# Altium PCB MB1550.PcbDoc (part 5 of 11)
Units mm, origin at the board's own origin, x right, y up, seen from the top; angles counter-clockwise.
Board outline 154.81 x 170.69 mm, 6 copper layers (Top Layer, Signal Layer 1, Signal Layer 2, Signal Layer 3, Signal Layer 4, Bottom Layer), stack 1.49 mm thick; 810 components, 633 nets, 2973 pads, 2150 vias.
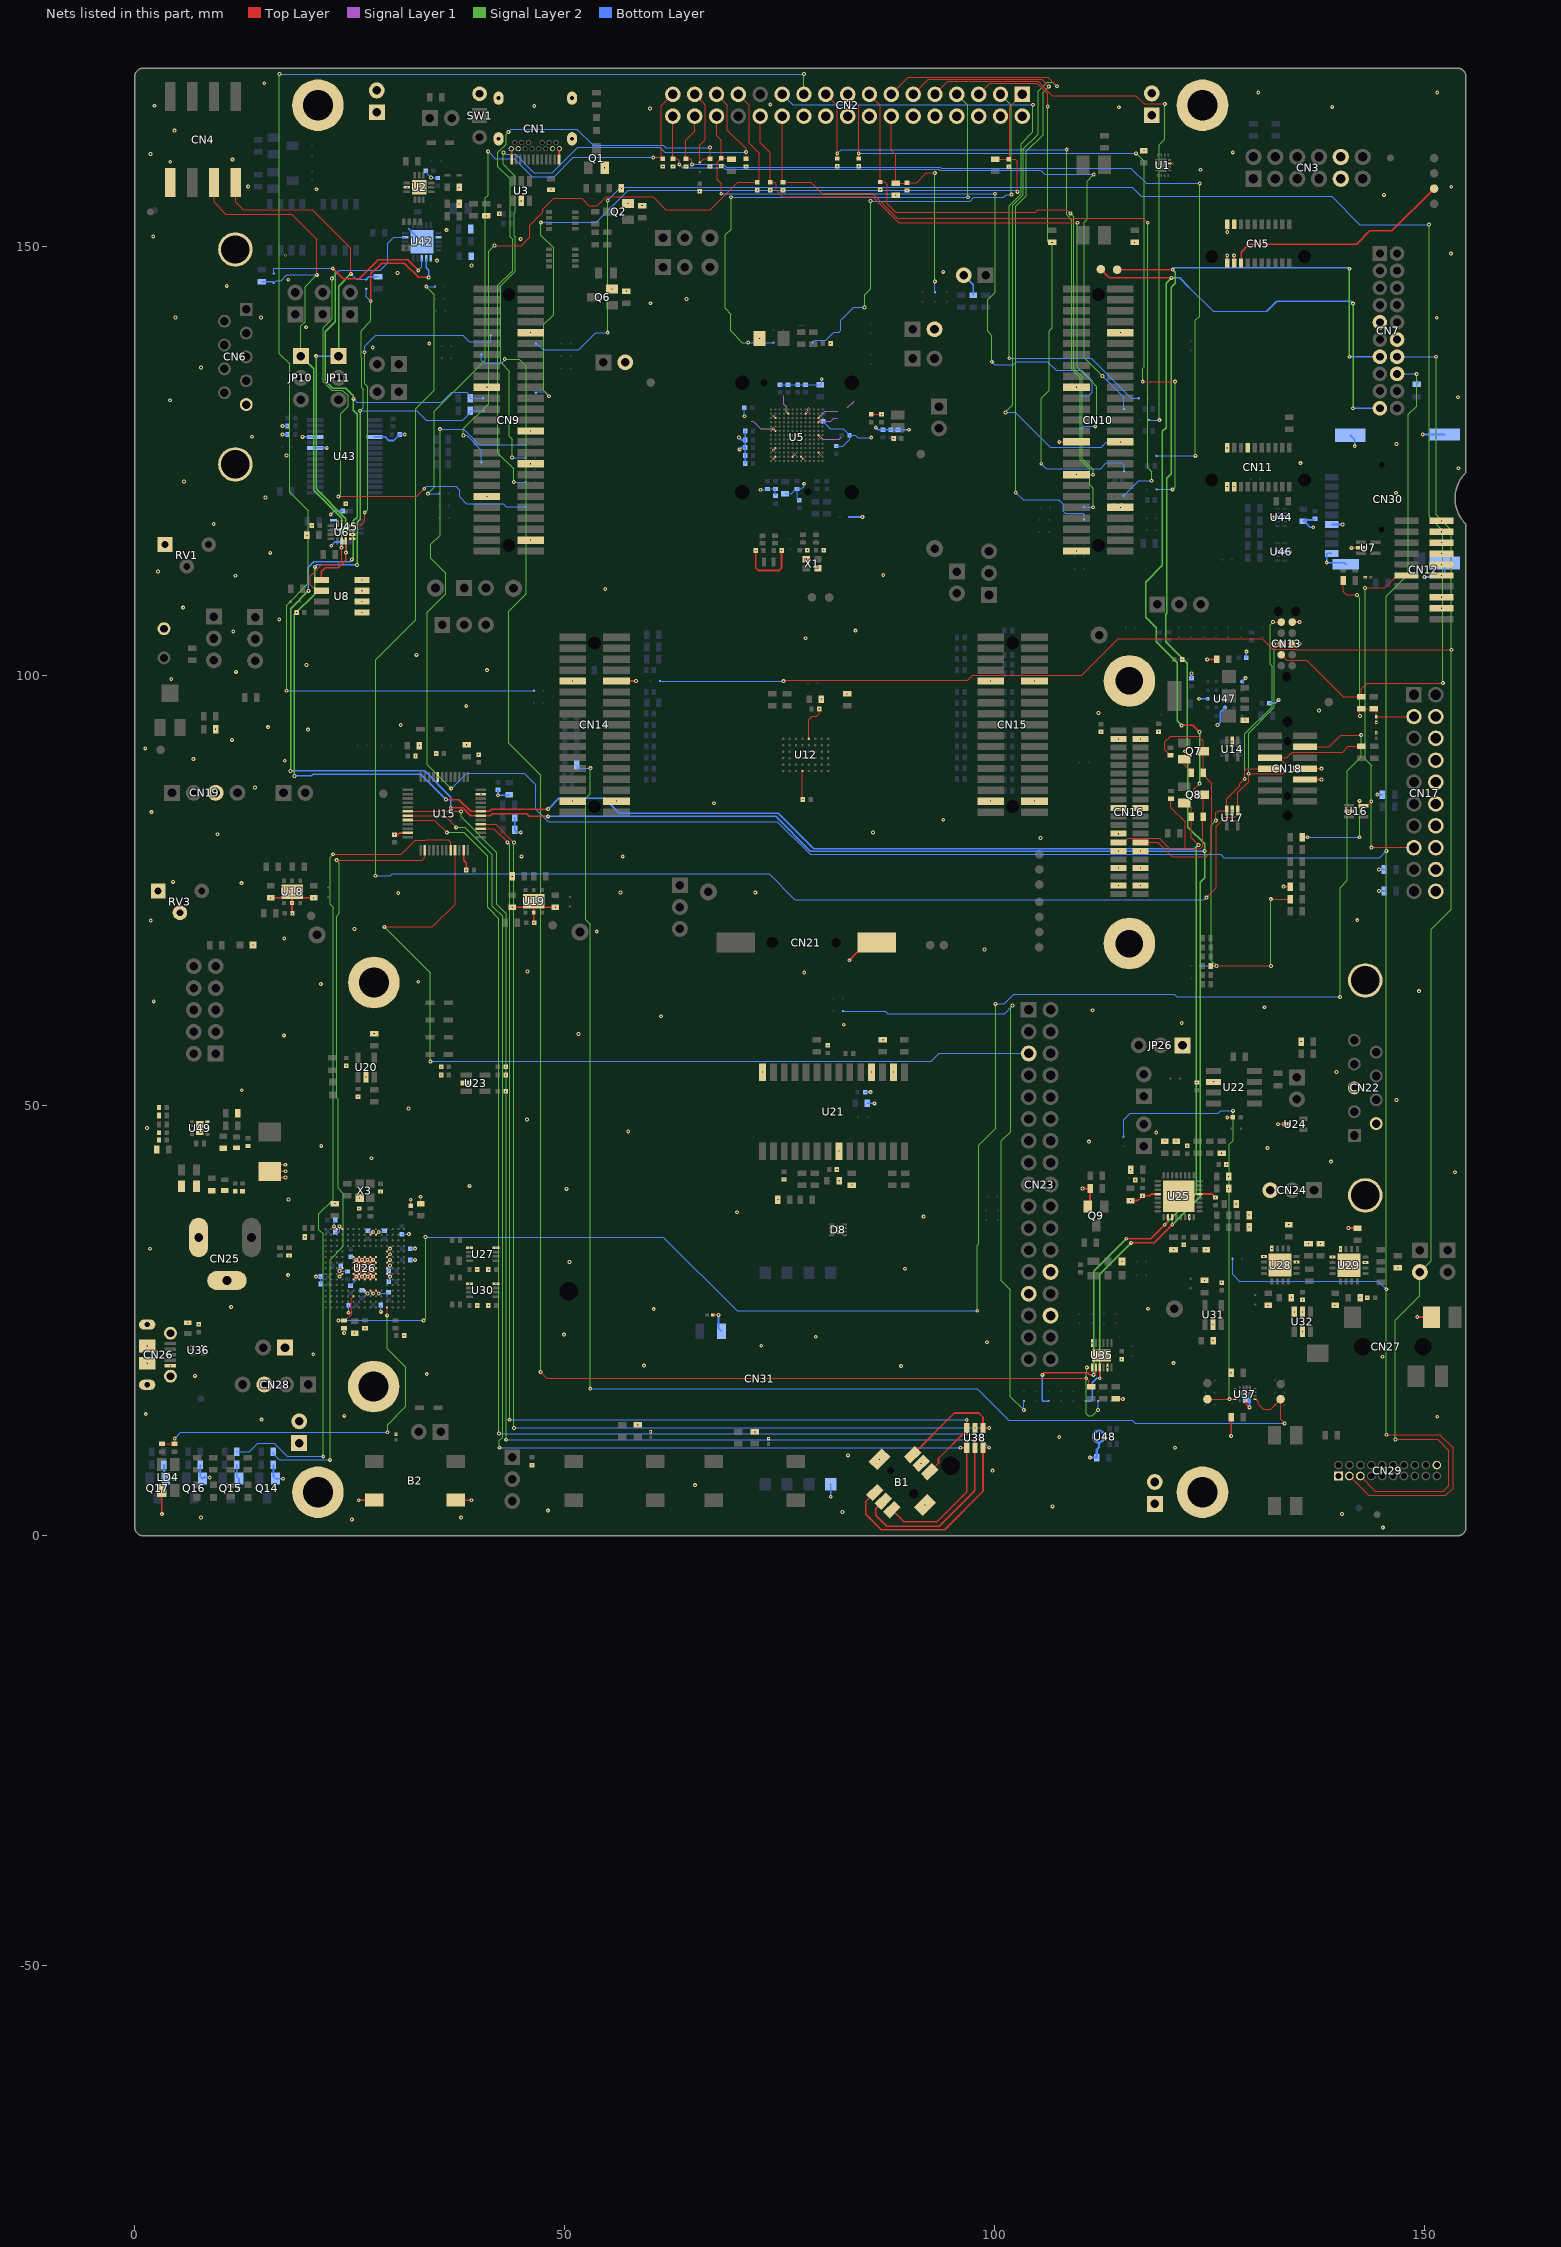
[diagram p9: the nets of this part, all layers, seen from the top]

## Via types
v1: diameter 0.45, hole 0.2, Top Layer to Bottom Layer, tented both sides, 1777 vias
v2: diameter 0.25, hole 0.1, Top Layer to Signal Layer 1, tented top, 344 vias
v3: diameter 0.25, hole 0.1, Signal Layer 1 to Signal Layer 2, 29 vias

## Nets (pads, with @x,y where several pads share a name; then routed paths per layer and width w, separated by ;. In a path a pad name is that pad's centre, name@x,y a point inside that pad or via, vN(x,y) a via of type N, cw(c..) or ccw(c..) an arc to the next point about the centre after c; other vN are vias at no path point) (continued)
GND: B1.5 B1.7 B1.8 B2.3 B2.4 C1.1 C2.1 C3.1 C4.2 C5.1 C6.2 C7.1 C8.2 C9.2 C10.2 C11.2 C12.1 C13.1 C14.1 C15.1 C16.1 C17.2 C18.1 C20.2 C21.2 C22.1 C23.1 C24.1 C25.1 C26.1 C27.1 C28.2 C29.2 C30.2 C31.2 C32.1 C33.1 C34.1 C35.1 C36.1 C37.1 C38.1 C39.1 C40.2 C41.1 C42.1 C43.1 C44.1 C45.1 C46.1 C47.1 C48.1 C49.1 C50.2 C51.2 C52.2 C54.2 C55.2 C56.1 C57.1 C58.2 C59.2 C60.2 C61.2 C62.1 C63.2 C64.2 C65.2 C67.2 C68.2 C69.1 C70.2 C71.2 C72.1 C73.1 C74.1 C75.2 C76.1 C77.1 C78.2 C79.2 C80.1 C81.1 C82.2 C83.2 C85.1 C87.2 C89.1 C90.2 C91.1 C94.2 C95.1 C96.1 C97.1 C98.2 C99.1 C100.1 C101.2 C102.2 C103.1 C104.2 C105.1 C106.1 C107.1 C108.1 C109.1 C110.2 C111.1 C112.1 C113.1 C116.2 C117.1 C118.1 C119.1 C120.1 C121.1 C122.1 C123.1 C124.1 C127.1 C128.1 C129.1 C130.1 C131.1 C132.1 C133.2 C134.1 C135.1 C136.1 C137.1 C138.1 C139.1 C142.1 C143.1 C144.1 C145.2 C146.1 C147.1 C150.2 C151.1 C152.1 C153.2 C154.1 C155.1 C156.1 C157.1 C158.2 C159.2 C160.1 C161.2 C162.2 C163.2 C164.2 C165.2 C166.2 C167.2 C168.2 C169.2 C170.2 C171.1 C172.2 C173.2 C174.2 C175.2 C176.2 C177.1 C178.2 C179.2 C180.1 C181.2 C185.1 C186.1 C187.1 C188.1 C189.1 CN1.A1 CN1.A12 CN1.B1 CN1.B12 CN1.SH1 CN1.SH2 CN1.SH3 CN1.SH4 CN2.2 CN2.4 CN2.6 CN2.8 CN2.10 CN2.12 CN2.16 CN2.18 CN2.20 CN2.22 CN3.5 CN3.11 CN4.2 CN5.17 CN5.18 CN5.19 CN5.20 CN6.5 CN6.MT1 CN6.MT2 CN7.5 CN7.16 CN8.2 CN9.10 CN9.19 CN9.28 CN9.34 CN9.39 CN9.48 CN10.10 CN10.19 CN10.29 CN10.30 CN10.35 CN10.42 CN10.49 CN11.13 CN11.18 CN11.19 CN11.20 CN12.3 CN12.5 CN12.9 CN12.11 CN12.13 CN12.15 CN12.17 CN12.19 CN13.3 CN13.5 CN14.9 CN14.10 CN14.31 CN14.32 CN15.9 CN15.10 CN15.31 CN15.32 CN16.3 CN16.4 CN16.7 CN16.8 CN16.11 CN16.12 CN16.16 CN16.21 CN16.22 CN16.37 CN16.38 CN16.41 CN16.42 CN17.4 CN17.6 CN17.8 CN17.10 CN17.12 CN17.14 CN17.16 CN17.18 CN17.20 CN18.5 CN18.7 CN19.3 CN21.2 CN22.3 CN22.6 CN22.MT1 CN22.MT2 CN23.26 CN23.27 CN23.30 CN24.3 CN26.5 CN26.6 CN26.7 CN26.8 CN26.9 CN26.10 CN26.11 CN27.3 CN28.3 CN29.1 CN29.20 CN30.6 CN30.9 CN30.11 CN30.12 CN30.13 CN30.14 CN31.C5 CN31.S1 D8.9 H1.1 H2.1 H3.1 H4.1 H5.1 H6.1 JP1.1 JP1.2 JP2.1 JP2.2 JP9.2 JP13.2 JP26.1 JP32.1 JP33.1 JP33.2 JP36.1 JP36.2 L3.1 LD2.2 LD4.1 Q1.2 Q2.2 Q6.2 Q9.2 Q14.2 Q15.2 Q16.2 Q17.2 R7.1 R9.2 R10.2 R12.1 R13.1 R16.1 R17.1 R20.1 R33.1 R38.2 R42.1 R44.1 R45.1 R60.1 R61.1 R73.1 R75.1 R77.1 R84.1 R85.1 R88.1 R93.1 R94.1 R96.1 R98.1 R99.1 R101.2 R102.2 R105.1 R107.1 R109.1 R115.1 R117.1 R118.2 R121.1 R122.2 R124.1 R126.1 R141.1 R230.1 R233.1 R234.1 R235.1 R236.1 R241.1 R242.1 R243.1 R244.1 R250.1 R251.1 R252.2 RV1.1 RV3.1 RV3.2 SB2.2 SB76.1 SW1.3 U1.11 U2.2 U2.13 U3.2 U4.2 U5.B2 U5.B4 U5.B8 U5.B11 U5.E12 U5.F2 U5.H2 U5.J12 U5.M3 U5.M7 U5.M10 U5.M11 U6.1 U6.2 U6.3 U6.6 U6.7 U7.2 U8.1 U8.2 U8.3 U8.4 U9.2 U11.2 U12.D1 U12.E6 U13.2 U14.2 U15.8 U15.23 U15.35 U15.47 U16.2 U17.2 U18.2 U18.EP U19.2 U19.EP U20.2 U21.2 U21.4 U21.14 U21.22 U22.2 U23.2 U24.3 U25.7 U25.13 U25.28 U25.33 U26.D5 U26.D6 U26.D7 U26.D8 U26.D9 U26.F2 U26.F6 U26.F7 U26.F8 U26.F9 U26.F10 U26.F12 U26.G2 U26.G6 U26.G7 U26.G8 U26.G9 U26.G10 U26.G12 U26.H6 U26.H7 U26.H8 U26.H9 U26.H10 U26.H12 U26.J6 U26.J7 U26.J8 U26.J9 U26.J10 U26.K6 U26.K7 U26.K8 U26.K9 U26.K10 U26.M1 U26.M8 U26.M9 U26.N1 U27.4 U27.5 U28.7 U28.12 U28.13 U28.17 U29.7 U29.12 U29.13 U29.17 U30.4 U30.5 U31.2 U32.2 U32.5 U32.6 U33.2 U34.2 U35.6 U35.11 U35.13 U36.3 U37.11 U38.2 U39.2 U40.2 U41.2 U42.12 U42.16 U42.21 U43.4 U43.23 U43.25 U44.3 U44.8 U45.4 U46.3 U46.8 U47.B3 U47.C1 U47.E5 U48.3 U49.8 U49.9 U51.2 X1.2 X1.4 X3.2 | length 267.7
  Top Layer w0.08: U5.F2@76.5,125.5 v2(76.75,125.75)
  Top Layer w0.1: v1(24.35,23.586) R117.1@24.35,24.15 ; C82.2@32.1,38.4 v1(32.1,39.095) ; C81.1@33.25,38.65 v1(33.25,39.434) ; U12.D1@77.65,88.946 77.65,85.675 v2(77.7,85.625) ; U12.E6@78.4,92.696 78.4,94.925 78.775,95.3 79.3,95.3 79.6,95.6 v2(79.6,96.15) ; C23.1@85.655,130.427 C22.1@86.825,130.427
  Top Layer w0.2: v1(3.15,2.524) LD4.1@3.15,5.3 ; v2(15.8,74.2) 17.85,74.2 U18.EP@18.3,74.65 ; v1(17.513,43.154) 16.5,43.154 C60.2@15.743,42.397 ; v1(17.534,42.397) C60.2@15.743,42.397 ; v1(17.539,41.666) 16.385,41.666 C60.2@15.699,42.353 C60.2@15.743,42.397 ; v2(18.35,72.4) 18.3,72.45 v2(18.3,73.6) U18.EP@18.3,74.65 ; v2(20.8,74.2) 18.75,74.2 U18.EP@18.3,74.65 ; v1(23.175,36) U26.N1@23.5,35.675 ; v1(23.825,30.15) U26.M9@24.15,30.475 ; v1(23.825,30.8) U26.M8@24.15,31.125 ; v1(23.825,36) U26.M1@24.15,35.675 ; U26.K10@25.45,29.825 v1(25.775,30.15) ; v1(25.775,30.15) U26.J10@26.1,29.825 v1@26.425,30.15 ; v1(26.05,4.15) B2.3@27.85,4.15 ; v1(26.425,30.15) U26.H10@26.75,29.825 v1(27.075,30.15) U26.H9@26.75,30.475 ; U26.H12@26.75,28.525 v1(27.075,28.2) ; U26.G12@27.4,28.525 v1(27.725,28.2) ; U26.G2@27.4,35.025 v1(27.725,35.35) ; U26.F7@28.05,31.775 v1(27.725,32.1) ; U26.F2@28.05,35.025 v1(28.375,35.35) ; U26.F12@28.05,28.525 v1(28.375,28.2) ; U26.F10@28.05,29.825 v1(27.725,30.15) ; U26.F7@28.05,31.775 v1(27.725,31.45) ; U26.F6@28.05,32.425 v1(27.725,32.1) ; U26.D9@29.35,30.475 v1(29.675,30.15) ; U26.D8@29.35,31.125 v1(29.675,31.45) ; U26.D7@29.35,31.775 v1(29.675,32.1) ; U26.D6@29.35,32.425 v1(29.675,32.75) ; U26.D5@29.35,33.075 v1(29.675,33.4) ; v2(30.2,81.55) 30.6,81.55 30.8,81.75 U15.23@31.748,81.75 ; B2.4@37.35,4.15 v1(39.15,4.15) ; U15.35@38.248,79.75 38.248,78.577 38.55,78.275 v2(38.55,77.45) ; CN1.B1@43.79,161.32 43.84,161.27 CN1.A12@43.84,160.07 ; v2(43.9,73.1) 45.7,73.1 v2(46.4,73.8) ; v2(46.45,71.3) 46.4,71.35 U19.2@46.4,72.5 v2(46.4,73.8) ; v2(48.9,73.1) 47.1,73.1 v2(46.4,73.8) ; CN1.A1@49.34,160.07 49.34,161.27 CN1.B12@49.39,161.32 ; CN14.10@56.025,99.41 v1(58.295,99.41) ; U33.2@67.213,25.7 v1(67.88,25.7) ; v2(72.225,114.6) 72.225,112.564 72.514,112.275 74.95,112.275 75.225,112.55 v2(75.225,114.6) ; v2(74.25,125.25) U5.B2@74.5,125.5 ; v2(74.25,126.25) U5.B4@74.5,126.5 ; v2(74.25,128.75) U5.B8@74.5,128.5 ; v2(74.25,130.25) U5.B11@74.5,130 ; v2(75.75,130.75) U5.E12@76,130.5 ; U5.H2@77.5,125.5 v2(77.75,125.25) ; U5.J12@78,130.5 v2(78.25,130.75) ; U5.M3@79.5,126 v2(79.75,125.75) ; U5.M7@79.5,128 v2(79.75,127.75) ; U5.M10@79.5,129.5 v2(79.75,129.75) ; U5.M11@79.5,130 v2(79.75,130.25) ; v1(83.104,66.934) 85.17,69 CN21.2@86.283,69 ; C22.1@86.825,130.427 v2(86.83,130.427) ; v1(107.52,127.225) CN10.29@109.523,127.225 ; v1(110.217,40.4) R93.1@111.1,40.4 111.1,38.55 Q9.2@110.85,38.3 ; R121.1@114.1,15.925 v1(114.908,15.925) ; v2(115.8,39) 116.65,39 C78.2@117.2,39.55 118.025,39.55 118.225,39.75 U25.28@118.975,39.75 ; U1.11@120.35,159.6 v2(120.7,159.6) ; U25.13@123.825,39.75 125.3,39.75 v2(125.7,39.35) ; v1(124.711,101.925) C33.1@125.85,101.925 ; v1(127.046,48.675) C63.2@127.7,48.675 ; CN5.20@127.05,148.025 v1(127.05,148.896) ; v1(127.05,151.625) CN5.19@127.05,152.525 ; v1(127.5,11.625) R122.2@127.5,13.8 ; CN5.18@127.85,148.025 v1(127.85,148.896) ; U37.11@129.3,15.725 129.3,15.275 v1(129.625,14.95) ; v1(132.955,47.875) U24.3@133.975,47.875 ; v1(133.582,75.5) R61.1@134.35,75.5 ; CN13.3@134.61,103.725 v1(135.468,103.725) ; CN13.5@134.61,106.265 v1(135.468,106.265) ; CN18.5@136.082,87.955 v1(138.015,87.955) ; CN18.7@136.082,89.225 v1(138.015,89.225) ; v1(141.143,35.8) C87.2@142.2,35.8 ; v1(141.514,114.9) U7.2@142.6,114.9 ; v1(149.152,25.45) CN27.3@150.8,25.45 ; U26.K8@25.45,31.125 v1(25.775,31.45) ; U26.K8@25.45,31.125 v1(25.775,30.8) ; U26.K8@25.45,31.125 v1(25.775,30.8) ; U26.K7@25.45,31.775 v1(25.775,32.1) ; U26.K7@25.45,31.775 v1(25.775,31.45) ; U26.K7@25.45,31.775 v1(25.775,31.45) ; v1(25.775,30.15) U26.K9@25.45,30.475 v1(25.775,30.8) ; v1(25.775,30.15) U26.J9@26.1,30.475 ; v1(25.775,30.8) U26.J9@26.1,30.475 ; v1(25.775,30.8) U26.J8@26.1,31.125 ; v1(25.775,31.45) U26.J7@26.1,31.775 ; v1(25.775,31.45) U26.J8@26.1,31.125 ; v1(25.775,32.1) U26.K6@25.45,32.425 v1(25.775,32.1) ; v1(25.775,32.1) U26.J7@26.1,31.775 ; v1(25.775,32.1) U26.J6@26.1,32.425 ; U26.J9@26.1,30.475 v1@26.425,30.8 ; U26.J9@26.1,30.475 v1@26.425,30.15 ; U26.J9@26.1,30.475 v1@26.425,30.15 ; U26.J8@26.1,31.125 v1@26.425,30.8 ; U26.J8@26.1,31.125 v1@26.425,30.8 ; U26.J8@26.1,31.125 v1@26.425,31.45 ; U26.J7@26.1,31.775 v1@26.425,32.1 ; U26.J7@26.1,31.775 v1@26.425,31.45 ; U26.J7@26.1,31.775 v1@26.425,31.45 ; U26.J6@26.1,32.425 v1@26.425,32.1 ; U26.J6@26.1,32.425 v1@26.425,32.1 ; v1@26.425,30.15 U26.H9@26.75,30.475 ; v1(26.425,30.8) U26.H9@26.75,30.475 ; v1@26.425,30.8 U26.H8@26.75,31.125 ; v1@26.425,31.45 U26.H8@26.75,31.125 ; v1@26.425,31.45 U26.H7@26.75,31.775 ; v1(26.425,32.1) U26.H7@26.75,31.775 ; v1@26.425,32.1 U26.H6@26.75,32.425 ; U26.H9@26.75,30.475 v1(27.075,30.8) ; U26.H9@26.75,30.475 v1(27.075,30.15) ; U26.H8@26.75,31.125 v1(27.075,30.8) ; U26.H8@26.75,31.125 v1(27.075,31.45) ; U26.H8@26.75,31.125 v1(27.075,30.8) ; U26.H7@26.75,31.775 v1(27.075,32.1) ; U26.H7@26.75,31.775 v1(27.075,31.45) ; U26.H7@26.75,31.775 v1(27.075,31.45) ; U26.H6@26.75,32.425 v1(27.075,32.1) ; U26.H6@26.75,32.425 v1(27.075,32.1) ; v1(27.075,30.15) U26.G9@27.4,30.475 ; v1(27.075,30.15) U26.G10@27.4,29.825 v1(27.725,30.15) ; v1(27.075,30.8) U26.G9@27.4,30.475 ; v1(27.075,30.8) U26.G8@27.4,31.125 ; v1(27.075,30.8) U26.G9@27.4,30.475 ; v1(27.075,31.45) U26.G8@27.4,31.125 ; v1(27.075,31.45) U26.G7@27.4,31.775 ; v1(27.075,32.1) U26.G7@27.4,31.775 ; v1(27.075,32.1) U26.G6@27.4,32.425 v1(27.725,32.1) ; U26.G9@27.4,30.475 v1(27.725,30.8) ; U26.G9@27.4,30.475 v1(27.725,30.15) ; U26.G9@27.4,30.475 v1(27.725,30.15) U26.F9@28.05,30.475 v1(27.725,30.8) ; U26.G8@27.4,31.125 v1(27.725,31.45) ; U26.G8@27.4,31.125 v1(27.725,30.8) ; U26.G8@27.4,31.125 v1(27.725,30.8) ; U26.G7@27.4,31.775 v1(27.725,32.1) ; U26.G7@27.4,31.775 v1(27.725,31.45) ; U26.G7@27.4,31.775 v1(27.725,31.45) ; v1(27.725,30.8) U26.F8@28.05,31.125 v1(27.725,31.45)
  Signal Layer 1 w0.08: 71.675,129.65 71.92,129.65 72.82,128.75 v2(74.25,128.75) ; v2(75.75,130.75) 75.75,131.364 ; v2(78.25,130.75) 78.25,131.075 78.4,131.225 ; v2(79.75,127.75) 79.993,127.507 81.915,127.507 82.171,127.763 ; 82.885,131.163 83.698,131.976
  Signal Layer 1 w0.1: 75.5,132.6 75.5,131.614 75.75,131.364 ; v2(79.75,129.75) 79.86,129.64 80.915,129.64 81.275,130 81.725,130 ; v2(79.75,130.25) 80.31,130.81 81.76,130.81
  Bottom Layer w0.08: v1(70.9,130.206) C123.1@70.9,131.2 ; C122.1@75.025,133.875 C121.1@75.975,133.875 C120.1@77.1,133.875 C119.1@78,133.875 C118.1@79.725,133.875 79.899,134.049 v1(79.899,134.505) ; C136.1@81.577,126.743 82.328,126.743 83.125,127.54 C134.1@83.125,128 83.794,128 84.076,127.718 v1(85.65,127.718)
  Bottom Layer w0.1: v1(21.075,30.15) C172.2@21.65,30.15 C174.2@21.65,29.3 ; v1(23.175,36) 23.175,36.6 C161.2@23.3,36.725 ; C165.2@23.3,35.325 23.7,35.325 23.825,35.45 v1(23.825,36) ; C169.2@23.95,31.375 23.825,31.25 v1(23.825,30.8) 24.525,30.8 C171.1@24.6,30.725 ; v1(24.875,25.95) C179.2@24.875,26.825 ; C175.2@25.075,29.1 25.775,29.8 v1(25.775,30.15) ; C167.2@25.125,32.45 25.475,32.1 v1(25.775,32.1) ; C176.2@26.425,28.55 26.425,28.525 26.75,28.2 v1(27.075,28.2) ; C164.2@27.1,35.475 27.225,35.35 v1(27.725,35.35) ; v1(28.375,28.2) 29.372,28.2 C177.1@29.493,28.32 ; v1(28.375,35.35) 28.925,35.35 C163.2@29.05,35.475 ; v1(28.625,26.05) C178.2@28.625,26.85 ; C173.2@29.55,29.55 29.675,29.675 v1(29.675,30.15) ; C170.2@29.55,30.8 29.675,30.925 v1(29.675,31.45) ; C162.2@31.05,35.1 v1(31.875,35.1) ; C168.2@32.025,32.1 v1(32.6,32.1) ; C166.2@32.025,33.4 v1(32.6,33.4) ; C144.1@73.575,121.75 74.437,121.75 C143.1@74.467,121.721 ; C143.1@74.5,121.75 74.5,121.089 C146.1@74.563,121.026 ; C145.2@75.625,121.175 76.367,121.175 C142.1@76.78,121.588 ; C142.1@77.068,121.78 C142.1@77.068,121.75 ; C142.1@77.185,121.935 C142.1@77,121.75 C142.1@77.068,121.75 ; C147.1@77.275,120.45 77.068,120.657 C142.1@77.068,121.75 ; v1(77.85,122.35) 77.85,122.075 77.525,121.75 C142.1@77.068,121.75 ; C124.1@80.022,129.624 80.885,128.76 82.365,128.76 C134.1@83.125,128
  Bottom Layer w0.12: C112.1@33.83,158.763 34.019,158.574 34.019,158.402 v1(34.457,157.963) 35.176,157.963 C113.1@35.234,157.906
  Bottom Layer w0.13: v1(72.775,121.65) 73.469,121.65 73.472,121.647 C144.1@73.575,121.75
  Bottom Layer w0.2: R244.1@3.4,8.275 3.4,6.875 Q17.2@3.625,6.65 v1(4.5,6.65) ; R243.1@7.625,8.275 7.625,6.9 Q16.2@7.875,6.65 8.025,6.8 v1(8.725,6.8) ; R242.1@11.875,8.275 11.875,6.9 Q15.2@12.125,6.65 v1(12.125,5.55) ; R241.1@16.125,8.275 16.125,6.9 Q14.2@16.375,6.65 v1(17.25,6.65) ; v1(17.2,128.075) C133.2@17.8,128.075 ; v1(17.2,129.075) C127.1@17.8,129.075 ; v1(19.511,127.811) U43.25@20.976,127.811 ; U43.23@20.976,126.511 20.99,126.525 v1(22.325,126.525) ; v1(22.795,118.791) 23.178,119.175 C151.1@24.2,119.175 ; v1(22.85,115.15) 23.275,115.575 C153.2@24.15,115.575 ; U43.4@27.876,127.811 29.114,127.811 29.55,127.375 30.1,127.375 C132.1@30.8,128.075 v1(31.4,128.075) ; 31.875,152.025 U42.21@33.4,150.5 U42.21@33.475,150.5 ; C158.2@42.25,86.75 v1(42.25,86.125) 43.475,86.125 C157.1@43.55,86.2 ; R234.1@44.2,82.125 44.327,81.998 44.327,81.819 v1(44.896,81.819) ; R234.1@44.2,82.125 R233.1@44.2,83.575 ; v1(67.88,25.7) 67.88,24.16 CN31.S1@68.24,23.8 ; v1(70.283,127.732) 70.565,127.45 C135.1@71,127.45 ; v1(70.349,126.352) 70.572,126.575 C137.1@71,126.575 ; C139.1@71,124.725 C138.1@71,125.65 C137.1@71,126.575 ; C131.1@71,128.5 C135.1@71,127.45 ; v1(80.94,4.544) v2(80.94,6) ; SB76.1@83.1,118.475 v1(84.619,118.475) ; C159.2@84.95,51.6 v1(85.584,51.6) ; C160.1@85.2,50.3 v1(86.013,50.3) ; v1(86.171,128.914) 86.448,128.637 C129.1@87.013,128.637 C128.1@87.913,128.637 C130.1@88.763,128.637 v1(90.021,128.637) ; CN8.2@96.405,146.6 97.525,145.48 C117.1@97.525,144.3 ; C155.1@122.9,99.725 v1(122.9,100.3) ; v1(123.784,97.346) U47.C1@124.784,97.346 ; v1(125.925,94.3) 126.275,94.65 126.275,95.837 U47.B3@126.784,96.346 ; U47.E5@128.784,99.346 v1(129.188,99.75) ; C154.1@129.275,102.125 v1(129.275,102.825) ; C180.1@129.3,15.8 129.625,15.8 v1(129.625,14.95) ; C156.1@131.95,96.825 132.625,96.825 v1(133.025,97.225) ; v1(132.35,118.45) U44.3@132.915,118.45 U44.8@133.735,118.45 ; U46.3@132.915,114.425 U46.8@133.735,114.425 v1(134.375,114.425) ; v1(137.05,117.3) 136.675,117.3 136.225,117.75 136.225,117.8 136.025,118 C150.2@135.9,118 136.05,118.15 137.125,118.15 C152.1@137.25,118.275 ; CN30.9@139.198,114.262 138.685,114.262 138.625,114.202 v1(138.625,113.175) 140.66,113.175 CN30.14@140.848,112.987 ; CN30.6@139.198,117.612 v1(140.462,117.612) ; CN30.13@141.348,127.987 141.875,127.46 v1(141.875,126.725) ; v1(144.5,86.2) R230.1@145.1,86.2 ; v1(144.7,75) R236.1@145.3,75 ; v1(144.7,77.5) R235.1@145.3,77.5 ; v1(149.788,128.087) CN30.12@152.348,128.087 ; v1(149.975,111.5) 151.925,111.5 152.348,111.923 CN30.11@152.348,113.137 ; C137.1@71,126.575 C135.1@71,127.45
  Bottom Layer w0.25: v1(111.075,9.1) C181.2@111.875,9.1 111.875,10.025 112.125,10.275 112.125,10.805
  other v1: 145.142,0.958 25.253,1.898 7.702,2.145 37.959,2.145 140.395,2.54 82.305,2.788 48.044,2.936 106.728,3.43 65.15,5.902 99.757,7.583 82.948,9.363 120.966,10.253 107.519,11.489 14.723,13.516 151.47,13.862 24.363,13.961 1.275,14.158 7.01,18.608 33.954,18.806 89.128,19.745 59.217,19.794 120.818,20.091 145.092,20.833 20.754,21.129 72.862,22.118 99.114,22.514 79.191,23.156 49.923,23.403 60.354,26.37 117.851,26.419 11.213,26.617 17.837,30.325 89.573,31.066 26.425,31.45 50.566,31.857 1.77,33.39 91.748,37.147 70.044,37.642 17.887,39.125 50.22,40.361 38.948,40.707 153.546,42.289 139.11,43.525 27.527,43.92 131.744,45.107 21.694,45.354 110.979,45.849 118.8,46.9 57.388,47.035 1.424,47.431 45.622,48.419 31.828,49.705 146.724,50.694 12.449,51.831 139.753,53.956 17.343,58.208 51.604,58.356 82.453,59.444 121.757,59.642 61.195,60.433 111.375,61.125 131.398,61.471 2.215,62.163 149.344,63.35 21.644,64.19 32.966,64.437 77.856,65.525 45.671,65.624 98.818,68.195 17.392,69.48 53.73,70.271 25.55,70.568 1.869,71.557 142.175,71.606 30.642,74.77 56.498,74.819 72.17,74.819 12.399,75.907 4.439,76.055 44.979,79.022 56.745,79.022 105.344,81.148 9.631,81.593 85.865,81.79 94.022,83.273 1.968,84.163 67.375,85.202 13.981,87.031 17.442,90.145 6.813,90.343 1.226,91.579 11.311,92.568 20.161,93.754 15.514,94.051 30.939,94.298 112.067,95.683 137.726,95.979 38.552,96.523 4.242,99.638 11.756,100.478 40.975,100.676 19.963,101.269 32.768,102.456 78.004,104.384 11.46,105.175 83.838,105.274 16.799,106.559 5.626,107.943 54.718,110.119 11.707,111.651 87.051,111.75 2.709,112.146 15.761,114.321 9.186,117.683 15.217,120.748 146.674,121.292 5.725,122.627 153.942,124.159 135.55,124.752 17.64,125.642 146.724,126.977 13.635,127.818 4.093,132.069 153.892,132.415 7.702,135.876 27.676,138.2 34.251,138.645 19.93,140.547 151.42,141.66 4.75,141.694 14.675,141.675 59.959,143.341 64.161,143.836 10.708,145.364 17.85,146.075 30.55,146.875 94.025,147 39.166,147.725 35.15,148.3 153.052,149.126 44.88,150.807 2.16,151.106 36.275,151.85 145.29,155.948 21.119,156.604 153.101,156.887 13.188,156.929 123.932,158.865 4.125,159.8 11.355,160.042 1.844,160.709 127.69,160.892 4.623,163.415 59.91,165.984 114.44,166.132 139.258,166.182 46.462,166.281 2.312,166.317 73.901,166.479 130.656,167.863 151.47,167.863 15.068,168.935
  other v2: 91.908,3.592 46.2,8.225 91.449,8.435 86.605,8.895 73.7,11.312 30.4,11.839 72.1,12.1 60,12.112 97.7,12.55 58.5,12.9 127.5,18.975 113.125,19.575 4.15,19.775 1.45,20.075 114.775,20.5 112.45,21 1.45,22.075 8.025,22.1 111.325,22.425 125.4,22.7 31.325,23.3 25.575,23.575 135.8,23.75 26.8,24.15 7.45,24.6 125.4,24.6 6.175,24.775 134.85,26.05 135.8,26.05 39.825,26.775 41.125,26.775 131.8,26.8 139.6,26.8 135.8,27.45 134.5,27.7 142.5,27.7 143.3,27.7 38.925,29.325 42.025,29.325 126.4,29.45 124.4,29.7 39.825,30.975 41.125,30.975 146.9,31.175 141.2,31.48 133.2,31.5 143.1,31.805 135.1,31.825 114.8,31.9 131.3,32.475 139.3,32.455 17.925,32.53 120.8,33.3 124.6,33.3 140.225,33.38 132.225,33.4 38.925,33.5 42.025,33.5 122,33.85 136.5,34 137.9,34 19.775,34.75 81.8,35.6 129.6,35.9 134.2,36.2 122.65,37.075 129.6,37.3 26.1,38.075 128.1,38.6 23.275,38.65 74.8,39.1 26.15,39.3 117.2,39.5 121.4,39.5 28.575,40 127.2,40.4 83.4,40.8 81.9,41.3 116.35,41.4 75.5,41.45 127.2,41.8 81.7,42.6 115.8,42.6 126.95,43.2 126.4,44.5 81.885,44.751 122.4,45.35 119.8,45.9 121.1,45.9 25.95,51.075 43.125,51.7 38.55,52.65 123.55,52.725 125.475,52.81 26.9,53.375 35.625,53.6 43.125,53.6 72.995,53.931 85.695,53.931 88.235,53.931 35.625,54.55 43.125,54.55 24.6,54.675 80.6,57.05 135.65,57.475 87,57.7 27.85,58.4 13.75,68.7 18.3,74.9 114.4,75.655 116.95,75.655 43.9,76.7 114.4,77.655 116.95,77.655 114.4,79.655 116.95,79.655 114.4,81.655 141.2,84.275 127.625,84.35 114.4,84.655 116.95,84.655 50.925,85.44 56.025,85.44 99.541,85.44 104.641,85.44 40.248,86.25 35.248,88.25 32.65,90.7 40,90.85 35.05,91 33.1,91.9 38.6,92 127.625,92.35 114.4,92.655 116.95,92.655 144.375,93.387 112.35,93.5 119.05,93.525 9.4,93.8 144.375,94.611 129.1,94.875 79.85,97.3 82.85,97.925 50.925,99.41 99.541,99.41 104.641,99.41 121.8,101.925 18.825,107.375 26.45,107.37 151.96,107.88 18.15,108.65 26.45,108.64 151.96,109.15 26.45,109.91 26.45,111.18 143.086,111.475 151.96,111.69 79.45,112.55 151.96,112.96 78.1,113.6 151.96,114.23 109.523,114.525 78.225,114.625 80.125,114.625 151.96,115.5 46.043,115.795 25.3,115.95 20.025,116.35 25.3,116.45 151.96,116.77 25.3,116.95 20.6,117.5 23.55,117.7 24.05,117.7 151.96,118.04 114.623,119.605 24.55,120.025 40.943,120.875 127.05,122.025 127.85,122.025 109.523,123.415 46.043,124.685 127.05,126.525 114.623,127.225 88.25,127.625 46.043,128.495 40.943,133.575 109.523,133.575 80.925,138.65 72.65,139.25 46.043,139.925 114.623,139.925 57.175,144.75 55.5,145 17.515,148.925 106.7,150.425 116.275,150.425 40.9,153.5 42.4,153.75 59.025,154.7 37.725,154.9 57.375,154.95 44.95,155.25 88.5,155.9 65.7,156.35 89.8,156.45 72.4,156.5 73.9,156.5 75.4,156.5 48.4,156.55 86.7,156.55 56.6,156.7 31.65,156.825 33.075,156.825 37.725,156.825 54.65,159.1 101.65,159.2 61.4,159.25 62.6,159.25 64.1,159.25 66.9,159.25 71.1,159.25 81.7,159.275 84.2,159.275 68.2,159.3 117.35,161.1
GND_EXT_UNFILT: C182.1 C183.1 C184.1 CN25.2 CN25.3 R252.1 U50.2
GNDDetect: CN18.11 R117.2 U26.K13 | length 207.4
  Top Layer w0.09: v1(23.675,25.05) R117.2@24.35,25.05 24.484,25.05 25.235,25.801 25.235,26.099 25.15,26.184 25.15,27.575 U26.K13@25.45,27.875
  Top Layer w0.12: CN18.11@136.082,91.765 138.915,91.765 140.275,93.125 v1(142.625,93.125)
  Signal Layer 2 w0.09: v1(33.6,25.05) 33.825,25.275 v1(33.825,34.75)
  Signal Layer 2 w0.12: v1(97.975,26.175) 97.975,33.8 98.125,33.95 98.125,45.415 100.1,47.39 v1(100.1,61.875) ; v1(140.175,62.675) 140.175,75.4 141,76.225 141,89 142.625,90.625 v1(142.625,93.125)
  Bottom Layer w0.09: v1(23.675,25.05) v1(33.6,25.05) ; v1(33.825,34.75) 35.05,34.75
  Bottom Layer w0.102: 35.05,34.75 61.475,34.75 70.05,26.175 v1(97.975,26.175)
  Bottom Layer w0.12: v1(100.1,61.875) 101.1,61.875 102.225,63 120.875,63 121.2,62.675 v1(140.175,62.675)
GYRO_ACC_INT: SB27.1 U6.4 | length 38.5
  Top Layer w0.12: U6.4@25.3,117.45 26.2,117.45 26.75,118 v1(26.75,119.025)
  Signal Layer 2 w0.12: v1(26.725,137.65) 26.725,134 27.075,133.65 27.075,119.35 v1(26.75,119.025)
  Bottom Layer w0.12: v1(26.725,137.65) 26.725,138.325 28,139.6 38.132,139.6 38.882,138.85 41.35,138.85 41.4,138.9 SB27.1@41.4,139.575
HOST_NRST: CN12.10 CN17.15 R53.1 U16.5 | length 54.1
  Top Layer w0.12: R53.1@135.75,81.25 v1(136.4,81.25) ; v1(142.45,85.475) 142.45,84.95 142.475,84.925 U16.5@142.9,84.925 143.113,84.713 v1(143.8,85.4) ; v1(143.075,110.24) 145.365,110.24 146.815,111.69 CN12.10@147.89,111.69 ; v1(143.825,80.04) 143.84,80.055 148.745,80.055 CN17.15@148.76,80.04
  Signal Layer 2 w0.12: v1(142.45,81.25) v1(142.45,85.475) ; v1(143.075,110.24) 143.075,90.3 143.825,89.55 143.8,89.525 v1(143.8,85.4) 143.8,80.065 v1(143.825,80.04)
  Bottom Layer w0.12: v1(136.4,81.25) v1(142.45,81.25)
I2C_SCL: CN7.7 Q7.2 R49.1 R147.1 SB13.1 SB46.1 SB138.2 TP8.1 U15.42 U25.3 U35.9 U42.18 | length 403.2
  Top Layer w0.12: Q7.2@122.025,90.175 Q7.2@122.05,90.2 ; v1(122.15,91.25) 122.15,90.3 Q7.2@122.05,90.2 ; R49.1@122.85,88.7 122.85,88.9 122.05,89.7 Q7.2@122.05,90.2
  Top Layer w0.15: v1(23.025,147.4) 24.25,146.175 26.125,146.175 28.325,148.375 31.772,148.375 v1(32.974,147.174) ; v1(36.75,84.675) 38.125,84.675 39.05,83.75 U15.42@40.248,83.75 41.35,83.75 41.55,83.95 45.6,83.95 45.875,83.675 v1(48.075,83.675) ; v1(112.225,18.325) U35.9@112.225,19.575 ; TP8.1@114.25,147.25 v1(120.714,147.25) ; v1(115.875,34.075) 118.55,34.075 v1(120.65,36.175) U25.3@120.65,37.075
  Signal Layer 2 w0.15: v1(18.125,88.95) 18.125,107.825 v1(20.2,109.9) ; v1(23.025,147.4) 23.345,147.08 23.345,141.17 22.18,140.005 22.18,134.354 23.054,133.48 24.545,133.48 25.425,132.6 v1(25.425,132.225) 25.425,130.875 25.85,130.45 25.85,118.46 25.425,118.035 25.425,113.725 v1(25.25,113.55) ; v1(112.225,18.325) 112.225,30.425 v1(115.875,34.075) ; v1(120.65,36.175) 123.919,39.444 123.919,76.019 124.425,76.525 v1(124.425,79.65) 124.425,80.475 122.475,82.425 122.475,90.95 v1@122.175,91.25 ; v1(120.714,147.25) 120.995,146.969 120.995,145.659 120.525,145.189 120.525,123.492 120.03,122.997 120.03,107.299 119.905,107.174 119.905,103.97 122.373,101.502 122.373,91.473 v1(122.15,91.25) ; v1(141.253,137.128) v1@141.253,147.35
  Bottom Layer w0.12: SB13.1@16.175,146.8 16.175,147.4 v1(23.025,147.4) ; v1(25.425,132.225) 25.8,131.85 35.715,131.85 36.85,132.985 38.59,132.985 39.025,132.55 R147.1@39.025,132.3 SB46.1@40.525,132.3 ; v1(32.974,147.174) 33.4,147.6 U42.18@33.4,148.5
  Bottom Layer w0.15: v1(18.125,88.95) 33.7,88.95 36.75,85.9 v1(36.75,84.675) ; v1(20.2,109.9) 20.2,112.66 20.844,113.305 25.005,113.305 v1(25.25,113.55) ; v1(48.075,83.675) 74.526,83.675 78.581,79.62 124.395,79.62 v1(124.425,79.65) ; SB138.2@110.6,15.675 111.175,15.675 111.325,15.825 111.325,17.8 111.85,18.325 v1(112.225,18.325) ; v1(120.714,147.25) 120.929,147.465 141.135,147.465 v1(141.25,147.35) ; v1(141.253,137.128) CN7.7@144.8,137.128
I2C_SCL_CAMERA: CN16.13 Q7.3 R48.1 R49.2 | length 29.2
  Top Layer w0.1: CN16.13@116.95,80.655 118.325,80.655
  Top Layer w0.12: 118.325,80.655 118.97,80.655 120.675,78.95 124.625,78.95 125.275,79.6 125.275,87.475 R49.2@124.2,88.55 ; R48.1@120.475,90.775 120.425,90.775 119.8,91.4 119.8,92.325 120.47,92.995 123.68,92.995 124.25,92.425 Q7.3@124.25,91.25 124.25,88.775 R49.2@124.225,88.75
I2C_SCL_SENSOR: CN4.6 JP10.1 R246.1 SB13.2 U6.13 U8.6 | length 70.7
  Top Layer w0.102: CN4.6@9.22,157.375 9.22,155.08 10.6,153.7 18.275,153.7 21.175,150.8 v1(21.175,146.65)
  Top Layer w0.12: U8.6@21.7,109.91 21.109,109.91 20.4,110.619 20.4,111.576 21.799,112.975 23.6,112.975 24.05,113.425 v1(24.05,114.925) U6.13@24.05,115.7
  Signal Layer 2 w0.12: JP10.1@19.325,137.2 19.325,140.725 19.81,141.21 19.81,145.285 v1(21.175,146.65)
  Signal Layer 2 w0.15: JP10.1@19.325,137.2 20.825,135.7 20.825,121.573 24.05,118.348 v1(24.05,114.925)
  Bottom Layer w0.12: SB13.2@16.175,145.7 16.456,145.981 17.031,145.981 17.7,146.65 v1(21.175,146.65)
  Bottom Layer w0.15: R246.1@14.756,145.828 16.035,145.828 16.163,145.7 SB13.2@16.175,145.7
I2C_SDA: CN7.10 Q8.2 R51.1 R149.1 SB14.1 SB49.1 SB141.2 TP7.1 U15.43 U25.2 U35.8 U42.17 | length 400.8
  Top Layer w0.12: Q8.2@122.575,84.925 122.85,84.65 R51.1@122.85,83.625 122.85,81.2 v1(123.7,80.35) ; Q8.2@122.7,85.7 123.15,86.15 123.15,86.8 v1(123.825,87.475)
  Top Layer w0.15: v1(27.45,143.575) 27.45,146.75 28.7,148 31.369,148 33.027,146.341 v1(34.181,146.341) ; v1(36.2,85.625) 37.675,85.625 39.05,84.25 U15.43@40.248,84.25 41.25,84.25 41.525,84.525 v1(48.075,84.525) ; v1(105.55,18.73) 105.784,18.964 110.814,18.964 111.048,18.73 v1(111.505,18.73) 111.775,19 U35.8@111.775,19.575 ; TP7.1@112.35,147.3 113.35,146.3 v1(120.575,146.3) ; v1(115.3,34.55) 118.15,34.55 120.15,36.55 U25.2@120.15,37.075 ; v1(121.745,94.25) 123.055,94.25 v1(123.825,93.48)
  Signal Layer 2 w0.12: v1(26.2,130.838) 26.58,131.218 26.58,133.345 26.415,133.51 26.415,136.95 26.32,137.045 26.32,140.164 27.45,141.294 v1(27.45,143.575)
  Signal Layer 2 w0.15: v1(18.575,88.375) 18.575,107.154 20.945,109.524 v1(20.945,112.694) ; v1(25.85,112.913) 25.85,117.9 26.2,118.25 v1(26.2,130.838) ; v1(111.505,18.73) 111.505,30.755 v1(115.3,34.55) ; v1(119.775,36.175) 123.442,39.842 123.442,80.092 v1(123.7,80.35) ; v1(120.575,146.3) 119.97,145.695 119.97,128.895 119.519,128.444 119.519,112.869 117.554,110.904 117.554,106.821 118.775,105.6 118.775,104 121.225,101.55 121.225,94.77 v1(121.745,94.25) ; v1(123.825,87.475) v1(123.825,93.48) ; v1(141.675,131.128) v1(141.675,143.3)
  Bottom Layer w0.12: v1(26.2,130.838) 26.2,130.825 26.205,130.83 32.77,130.83 33.875,129.725 38.15,129.725 39.008,130.583 R149.1@39.008,130.85 SB49.1@40.533,130.85 ; SB14.1@26.925,145.025 26.925,144.1 v1(27.45,143.575) ; 122.575,145.23 125.4,142.405 131.63,142.405
  Bottom Layer w0.15: v1(18.575,88.375) 20.55,88.375 20.75,88.575 33.25,88.575 v1(36.2,85.625) ; v1(20.945,112.694) 21.164,112.913 v1(25.85,112.913) ; U42.17@33.9,148.5 33.9,147.475 34.181,147.194 v1(34.181,146.341) ; v1(48.075,84.525) 49.32,85.77 54.58,85.77 56.325,84.025 74.814,84.025 78.949,79.89 123.24,79.89 v1(123.7,80.35) ; v1(105.55,18.73) 105.55,15.8 105.675,15.675 SB141.2@106.275,15.675 ; v1(120.575,146.3) 121.505,146.3 122.575,145.23 ; 131.63,142.405 132.799,143.574 141.401,143.574 v1(141.675,143.3) ; v1(141.675,131.128) CN7.10@144.8,131.128
I2C_SDA_CAMERA: CN16.14 Q8.3 R50.1 R51.2 | length 23.1
  Top Layer w0.1: CN16.14@114.4,80.655 114.97,80.655 115.47,81.155 118.325,81.155
  Top Layer w0.12: 118.325,81.155 119.12,81.155 120.35,79.925 122.15,79.925 ; R50.1@120.5,85.725 120.5,84.675 122.15,83.025 122.15,79.925 ; R51.2@124.2,83.625 124.2,80.2 123.925,79.925 122.15,79.925 ; R51.2@124.25,83.625 Q8.3@124.25,86.15
I2C_SDA_SENSOR: CN4.8 JP11.1 R245.1 SB14.2 U6.14 U8.5 | length 68
  Top Layer w0.102: CN4.8@11.76,157.375 11.76,155.09 12.625,154.225 20.625,154.225 25.135,149.715 v1(25.135,146.76)
  Top Layer w0.15: U8.5@21.7,111.18 21.7,112.125 22.15,112.575 23.65,112.575 24.55,113.475 U6.14@24.55,115.7
  Signal Layer 2 w0.15: v1(21.095,137.195) 21.095,121.755 24.55,118.3 v1(24.55,114.35) ; JP11.1@23.7,137.2 23.7,145.325 v1(25.135,146.76)
  Bottom Layer w0.12: v1(25.135,146.76) 25.77,146.125 SB14.2@26.925,146.125
  Bottom Layer w0.15: v1(21.095,137.195) 23.695,137.195 JP11.1@23.7,137.2 ; SB14.2@26.925,146.125 27.233,146.433 R245.1@28.295,146.433
IBUS_SENSE: SB72.2 U42.4 | length 63.6
  Top Layer w0.12: v1(23.675,120.875) 32.775,120.875 v1(33.675,121.775)
  Signal Layer 2 w0.12: v1(22.925,146.225) 22.955,146.195 22.955,141.515 21.925,140.485 21.925,134.234 22.934,133.225 24.158,133.225 24.805,132.578 24.805,131.38 23.94,130.515 23.94,121.14 v1(23.675,120.875)
  Bottom Layer w0.12: v1(22.925,146.225) 23.865,147.165 28.523,147.165 29.431,148.073 29.431,150.331 30.1,151 U42.4@31.4,151 ; v1(33.675,121.775) 33.95,122.05 37.325,122.05 37.775,121.6 37.775,120.85 38.575,120.05 42.85,120.05 43.225,119.675 SB72.2@45.45,119.675
INTn: CN5.16 TP3.1 | length 26.8
  Top Layer w0.15: CN5.16@128.65,148.025 128.65,149.3 129.546,150.196 142.086,150.196 143.639,151.75 146.175,151.75 TP3.1@151.1,156.675
JOY_DOWN: B1.3 U15.19 U38.4 | length 151.5
  Top Layer w0.12: U15.19@31.748,83.75 36.025,83.75 v1(37.375,82.4)
  Top Layer w0.2: B1.3@88.055,3.061 89.466,1.65 93.3,1.65 96.75,5.1 U38.4@96.75,10.25 v1(96.025,10.25)
  Signal Layer 2 w0.12: v1(37.375,82.4) 38.4,82.4 41.575,79.225 41.575,73.25 42.775,72.05 42.775,11.475 42.4,11.1 v1(42.4,10.25)
  Bottom Layer w0.12: v1(42.4,10.25) v1(96.025,10.25)
JOY_LEFT: B1.1 U15.20 U38.6 | length 161.4
  Top Layer w0.12: U15.20@31.748,83.25 34.85,83.25 v1(36.3,81.8)
  Top Layer w0.2: B1.1@86.075,5.041 85.025,3.992 85.025,2.5 86.797,0.728 94.203,0.728 98.65,5.175 U38.6@98.65,10.25 v1(99.375,10.25)
  Signal Layer 2 w0.12: v1(36.3,81.8) 38.25,81.8 41.024,79.026 41.024,73.076 42.35,71.75 v1(42.35,11.9)
  Bottom Layer w0.12: v1(42.35,11.9) 97.725,11.9 v1(99.375,10.25)
JOY_RIGHT: B1.6 U15.39 U38.3 | length 132
  Top Layer w0.12: U15.39@40.248,82.25 41.75,82.25 v1(43.35,80.65)
  Top Layer w0.2: B1.6@92.439,7.446 93.475,8.482 93.475,9 96.75,12.275 U38.3@96.75,12.55 v1(96.75,13.5)
  Signal Layer 2 w0.12: v1(43.35,80.65) 43.6,80.4 v1(43.6,13.5)
  Bottom Layer w0.12: v1(43.6,13.5) v1(96.75,13.5)
JOY_SEL: B1.2 U15.18 U38.5 | length 157.7
  Top Layer w0.12: U15.18@31.748,84.25 v1(37.95,84.25)
  Top Layer w0.2: B1.2@87.065,4.051 86.175,3.162 86.175,2.4 87.45,1.125 93.575,1.125 97.7,5.25 U38.5@97.7,10.25 v1(97.7,11.175)
  Signal Layer 2 w0.12: v1(37.95,84.25) 37.95,83.625 42.113,79.462 42.113,73.432 43.195,72.35 v1(43.195,11.175)
  Bottom Layer w0.12: v1(43.195,11.175) v1(97.7,11.175)
JOY_UP: B1.4 U15.40 U38.1 | length 140.5
  Top Layer w0.12: U15.40@40.248,82.75 41.975,82.75 v1(44.1,80.625)
  Top Layer w0.2: B1.4@90.459,9.425 95.333,14.3 98.125,14.3 98.65,13.775 U38.1@98.65,12.55 v1(99.375,12.55)
  Signal Layer 2 w0.12: v1(44.1,12.55) v1(44.1,80.625)
  Bottom Layer w0.12: v1(44.1,12.55) v1(99.375,12.55)
JTAG_TRST: CN17.3 R31.2 R40.1 R41.1 U11.1 | length 25
  Top Layer w0.12: R31.2@140.55,111.1 140.55,109.775 140.9,109.425 v1(142.15,109.425) ; v1(142.475,95.35) 142.475,96 R40.1@142.65,96.175 R41.1@144.1,96.175 144.375,95.9 U11.1@144.375,95.262 144.392,95.28 CN17.3@148.76,95.28
  Signal Layer 2 w0.12: v1(142.15,109.425) 142.475,109.1 v1(142.475,95.35)
JTDI: CN13.8 CN18.10 R46.2 SB15.2 U17.1 | length 222.6
  Top Layer w0.12: v1(124.625,74.225) 125.775,75.375 125.775,82.549 126.776,83.55 127.88,83.55 128.275,83.945 U17.1@128.275,84.35 128.275,86.475 129.525,87.725 v1(129.525,88.625) 133.5,88.625 133.825,88.95 133.825,89.725 CN18.10@133.055,90.495 ; CN18.10@132.018,90.495 CN18.10@133.055,90.495 ; v1(132.5,103.725) CN13.8@133.34,103.725 ; R46.2@142.65,91.825 141.15,91.825 140.475,91.15 134.6,91.15 133.945,90.495 CN18.10@133.055,90.495
  Signal Layer 2 w0.12: v1(28,76.775) 28,101.875 32.68,106.555 32.68,131.055 34.85,133.225 34.85,144.325 v1(33.9,145.275) ; v1(129.525,88.625) 129.525,93.35 132.171,95.996 132.52,96.345 132.52,103.705 v1(132.5,103.725)
  Bottom Layer w0.12: v1(28,76.775) 29.725,76.775 29.95,77 73.775,77 76.775,74 124.4,74 v1(124.625,74.225) ; v1(33.9,145.275) SB15.2@34.925,145.275
JTDO_SWO: CN13.6 CN18.8 R62.2 R70.1 SB114.2 U17.3 | length 67.8
  Top Layer w0.12: R70.1@125.125,66.275 v1(125.8,66.275) v1(132.125,66.275) ; v1(125.725,83.2) 125.725,84.075 126,84.35 U17.3@126.975,84.35 126.975,85.713 128.525,87.263 128.525,87.458 v1(129.092,88.025) 129.092,89 129.317,89.225 CN18.8@132.018,89.225 ; v1(132.12,74.05) R62.2@134.35,74.05 ; v1(132.38,106.265) CN13.6@133.34,106.265
  Signal Layer 2 w0.12: v1(125.725,83.2) 125.175,82.65 125.175,66.9 v1(125.8,66.275) ; v1(129.092,88.025) 129.092,93.256 132.28,96.444 132.28,101.143 132.071,101.351 132.071,105.956 v1(132.38,106.265) ; v1(132.12,74.05) 132.12,66.28 v1(132.125,66.275)
  Bottom Layer w0.12: SB114.2@123.975,66.275 v1(125.8,66.275)
JTRSTN: CN13.9 R40.2 SB32.2 | length 198.8
  Top Layer w0.12: CN13.9@133.34,102.455 133.97,101.825 136.3,101.825 140.55,97.575 R40.2@142.65,97.575 142.65,98.5 143.325,99.175 v1(152.125,99.175)
  Signal Layer 2 w0.12: v1(55,139.925) v1(55,155.3) ; v1(150.52,152.5) 150.52,118.505 152.125,116.9 v1(152.125,99.175)
  Bottom Layer w0.12: SB32.2@46.65,138.65 46.775,138.65 47.5,137.925 51.625,137.925 53.625,139.925 v1(55,139.925) ; v1(55,155.3) 56.546,156.846 90.51,156.846 90.514,156.85 116.025,156.85 117.075,155.8 139.175,155.8 142.475,152.5 v1(150.52,152.5)
LCD_CTP_INT: R119.1 SB35.2 SB137.2 U35.7 | length 199.9
  Top Layer w0.12: v1(47.2,19.05) 47.925,18.325 v1(110.65,18.325) 110.95,18.025 110.95,17.325 R119.1@111.225,17.325 ; v1(110.725,19.575) U35.7@111.325,19.575
  Signal Layer 2 w0.12: v1(43.025,136.85) 44.725,136.85 45.538,136.037 45.538,109.558 43.499,107.519 43.499,92.151 47.2,88.45 v1(47.2,19.05) ; v1(110.725,19.575) 110.725,19.05 110.65,18.975 v1(110.65,18.325) 110.65,14.225 110.9,13.975 111.35,13.975 v1(112.025,14.65)
  Bottom Layer w0.12: SB35.2@40.3,137.4 40.3,136.725 40.675,136.35 42.675,136.35 v1@43.1,136.775 ; v1(112.025,14.65) SB137.2@112.025,15.675
LCD_RESET: CN23.5 U15.33 | length 103.4
  Top Layer w0.1: v1(29.025,70.825) 34.625,70.825 37.248,73.448 U15.33@37.248,79.75
  Signal Layer 2 w0.09: v1(29.025,70.825) 34.375,65.475 v1(34.375,55.175)
  Bottom Layer w0.1: v1(34.375,55.175) 92.625,55.175 93.55,56.1 CN23.5@103.96,56.1
LCD_TE: SB117.2 SB143.2 | length 69.9
  Signal Layer 2 w0.12: v1(102.075,61.675) 101.875,61.475 101.875,47.025 100.792,45.942 100.792,29.683 101.842,28.633 101.842,16.208 v1(103.4,14.65)
  Bottom Layer w0.12: SB117.2@82.375,61.025 87.3,61.025 87.578,60.747 101.147,60.747 v1(102.075,61.675) ; v1(103.4,14.65) SB143.2@103.4,15.675
LED_BLUE: R238.1 U15.32 | length 97.7
  Top Layer w0.12: v1(23.075,79.275) 30.973,79.275 32.618,80.92 33.843,80.92 33.873,80.95 36.475,80.95 36.748,80.677 U15.32@36.748,79.75
  Signal Layer 2 w0.1: 21.925,22.525 21.925,35.125 21.425,35.625 21.425,37.45 23.075,39.1 23.075,42.05
  Signal Layer 2 w0.12: v1(21.925,9.25) 21.925,22.525 ; 23.075,42.05 23.075,73.125 22.725,73.475 22.725,78.925 v1(23.075,79.275)
  Bottom Layer w0.12: R238.1@11.875,9.775 13.325,9.775 14.3,10.75 16.25,10.75 17.75,9.25 v1(21.925,9.25)
LED_STLK: R128.2 R129.2 U26.D15 | length 43.5
  Top Layer w0.09: v1(29.35,25.65) U26.D15@29.35,26.575
  Top Layer w0.102: R129.2@4.65,10.7 v1(4.65,11.325)
  Top Layer w0.12: R128.2@3.15,10.7 R129.2@4.65,10.7
  Signal Layer 2 w0.09: 29.35,22.525 v1(29.35,25.65)
  Signal Layer 2 w0.102: 29.35,22.525 29.35,21.775 31.5,19.625 31.5,15.05 29.4,12.95 v1(29.4,12.05)
  Bottom Layer w0.102: v1(4.65,11.325) 5.375,12.05 v1(29.4,12.05)
LED_YELLOW: R237.1 U15.26 | length 89.4
  Top Layer w0.12: v1(23.47,78.58) 33.43,78.58 33.748,78.898 U15.26@33.748,79.75
  Signal Layer 2 w0.1: 22.725,22.525 22.725,32.125 24.275,33.675 24.275,39.8 23.65,40.425 23.65,42.05
  Signal Layer 2 w0.12: v1(22.725,8.845) 22.725,22.525 ; v1(23.47,78.58) 23.805,78.245 23.805,72.405 23.47,72.07 23.47,50.927 23.65,50.747 23.65,42.05
  Bottom Layer w0.12: R237.1@16.125,9.775 16.125,9.525 16.805,8.845 v1(22.725,8.845)
MC_BUS_VOLTAGE: C15.2 CN2.14 R7.2 SB17.2 | length 27
  Top Layer w0.12: CN2.14@87.982,165.1 87.982,161.143 88.5,160.625 R7.2@88.5,157.3 89.75,157.3 C15.2@89.8,157.35 ; C15.2@89.825,157.375 C15.2@89.8,157.35 ; v1(93.05,158.5) 92.075,158.5 90.925,157.35 C15.2@89.8,157.35
  Signal Layer 2 w0.12: v1(93.05,145.872) v1(93.05,158.5)
  Bottom Layer w0.12: SB17.2@93.05,144.625 v1(93.05,145.872)
MC_CURRENT_A: C11.1 CN2.15 SB63.2 | length 68.4
  Top Layer w0.12: CN2.15@85.442,167.64 86.7,166.381 C11.1@86.7,157.45 87.2,157.45 87.525,157.125 87.525,154.925 88.5,153.95 104.775,153.95 105.025,154.2 108.4,154.2 v1(108.8,153.8)
  Signal Layer 2 w0.12: v1(108.8,153.8) 109.22,153.38 109.22,135.755 110.175,134.8 110.175,125.247 111.45,123.972 v1(111.45,123.4)
  Bottom Layer w0.12: SB63.2@110.4,123.4 v1(111.45,123.4)
MC_CURRENT_B: C4.1 CN2.17 SB66.2 | length 85.5
  Top Layer w0.12: CN2.17@82.902,167.64 84.2,166.341 C4.1@84.2,160.175 ; v1(117.225,134.225) v1(120.975,134.225)
  Signal Layer 2 w0.12: v1(116.45,160.775) 117.38,159.845 117.38,135.925 117.225,135.77 v1(117.225,134.225) ; v1(120.7,121.7) 120.975,121.975 v1(120.975,134.225)
  Bottom Layer w0.12: v1(84.2,160.775) v1(116.45,160.775) ; SB66.2@118.825,121.7 v1(120.7,121.7)
MC_CURRENT_C: C3.2 CN2.19 SB73.2 | length 79
  Top Layer w0.12: CN2.19@80.362,167.64 81.7,166.301 C3.2@81.7,160.175
  Signal Layer 2 w0.12: v1(108.383,161.208) 108.383,153.608 108.98,153.011 108.98,135.656 109.935,134.701 109.935,125.148 111.045,124.038 111.045,122.255 111.45,121.85 v1(111.45,119.625)
  Bottom Layer w0.12: v1(81.7,160.775) 82.133,161.208 v1(108.383,161.208) ; 110.15,119.625 v1(111.45,119.625)
MC_DISSIPATIVE_BRAKE: CN2.23 SB45.2 | length 77.3
  Signal Layer 2 w0.12: v1(101.7,136.95) 101.7,154.7 103.08,156.08 103.08,161.905 104.45,163.275 v1(104.45,166.425)
  Bottom Layer w0.12: CN2.23@75.282,167.64 76.497,166.425 v1(104.45,166.425) ; v1(101.7,136.95) 111.238,136.95 115.888,132.3 SB45.2@116.75,132.3
MC_EMERGENCY_STOP: C10.1 CN2.1 R6.2 SB43.2 | length 94.9
  Top Layer w0.12: R6.2@100.05,160.1 C10.1@101.65,160.1 C10.1@101.762,160.1 ; v1(102.65,156.3) 102.65,159.85 102.4,160.1 C10.1@101.762,160.1 ; CN2.1@103.222,167.64 101.762,166.18 C10.1@101.762,160.1
  Signal Layer 2 w0.12: v1(47.225,152.75) 47.225,151.254 48.7,149.779 48.7,142.025 47.55,140.875 47.55,133.15 v1(48.175,132.525)
  Bottom Layer w0.12: 46.475,133.025 47.675,133.025 v1(48.175,132.525) ; v1(47.225,152.75) 53.65,152.75 57.4,156.5 102.45,156.5 v1(102.65,156.3)
MC_ENCODER_A: C8.1 CN2.31 SB1.1 SB65.2 | length 80.7
  Top Layer w0.12: CN2.31@65.122,167.64 66.35,166.412 66.35,162.375 65.7,161.725 SB1.1@65.7,159.7 66.15,160.15 C8.1@66.9,160.15 v1(66.9,161.45)
  Signal Layer 2 w0.12: v1(43.45,163.25) 43.185,162.985 43.185,161.861 42.22,160.896 42.22,159.23 43.65,157.8 43.65,151.075 43.95,150.775 43.95,147.15 42.23,145.43 42.23,125.92 44.075,124.075 v1(44.075,122.55)
  Bottom Layer w0.12: v1(43.45,163.25) 43.8,163.6 51.427,163.6 53.315,161.712 61.488,161.712 61.75,161.45 v1(66.9,161.45) ; v1(44.075,122.55) SB65.2@45.45,122.55
MC_ENCODER_B: C6.1 CN2.33 SB67.2 | length 74.4
  Top Layer w0.12: v1(60.3,160.3) C6.1@61.25,160.3 ; C6.1@61.4,160.15 C6.1@61.25,160.3 ; CN2.33@62.582,167.64 61.225,166.283 61.225,160.325 C6.1@61.25,160.3
  Signal Layer 2 w0.12: v1(34.1,121.2) 34.85,121.95 34.85,130.786 40.79,136.726 40.79,155.615 41.1,155.925 v1(41.1,161)
  Bottom Layer w0.12: v1(34.1,121.2) 35.387,121.2 SB67.2@35.412,121.225 ; v1(41.1,161) 41.925,160.175 44.111,160.175 46.226,158.06 48.771,158.06 51.011,160.3 v1(60.3,160.3)
MC_ENCODER_INDEX: C7.2 CN2.34 SB48.2 | length 84.5
  Top Layer w0.12: CN2.34@62.582,165.1 62.582,160.168 C7.2@62.6,160.15 63.1,160.15 63.325,159.925 v1(63.325,159.5)
  Signal Layer 2 w0.12: v1(111.525,158.325) 110.75,157.55 110.75,153.1 110.422,152.772 110.422,137.003 v1(112.55,134.875)
  Bottom Layer w0.12: v1(63.325,159.5) 63.73,159.095 68.486,159.095 68.676,158.905 93.52,158.905 93.612,158.813 105.35,158.813 105.838,158.325 v1(111.525,158.325) ; v1(112.55,134.875) 115.025,132.4 SB48.2@115.025,131.05
MC_ICL_SHUTOUT: CN2.21 SB107.2 | length 166.3
  Signal Layer 2 w0.12: v1(16.825,170) 16.825,137.5 18.005,136.32 18.005,130.52 18.045,130.48 18.045,121.353 20.195,119.203 20.195,110.756 17.65,108.211 v1(17.65,98.275) ; CN2.21@77.822,167.64 v1(77.822,170)
  Bottom Layer w0.12: v1(16.825,170) v1(77.822,170) ; v1(17.65,98.275) SB107.2@46.425,98.275
MC_PFC_IND_CURR: C14.2 CN2.24 SB69.2 | length 86.2
  Top Layer w0.12: CN2.24@75.282,165.1 75.282,157.518 C14.2@75.4,157.4 78.625,157.4 79.95,156.075 85.839,156.075 88.689,153.225 117.275,153.225 v1(117.8,152.7)
  Signal Layer 2 w0.12: v1(117.8,152.7) 117.8,124.2 118.245,123.755 v1@118.245,122.701
  Bottom Layer w0.12: SB69.2@115.017,120.966 115.017,120.984 116.733,122.7 v1(118.25,122.7)
MC_PFC_PWM: C9.1 CN2.29 SB58.2 | length 78.5
  Top Layer w0.12: CN2.29@67.662,167.64 68.925,166.377 68.925,163.475 71.1,161.3 C9.1@71.1,160.15
  Signal Layer 2 w0.12: v1(42.875,160.875) 42.875,159.525 44.263,158.137 44.263,153.96 44.13,153.828 44.13,151.195 44.263,151.063 44.263,149 44.254,148.991 44.254,148.076 44.263,148.067 44.263,147.063 42.563,145.363 42.563,136.462 43.567,135.458 43.567,127.858 43.875,127.55 v1(43.875,125.4)
  Bottom Layer w0.12: v1(42.875,160.875) 43.095,160.655 44.309,160.655 46.424,158.54 48.572,158.54 51.504,161.472 61.068,161.472 61.614,160.925 v1(71.1,160.925) ; v1(43.875,125.4) SB58.2@45.45,125.4
MC_PFC_SHUTDOWN: C2.2 CN2.30 R5.1 SB44.2 | length 78.4
  Top Layer w0.12: CN2.30@67.662,165.1 67.662,162.813 68.2,162.275 C2.2@68.2,160.2 ; v1(68.2,156.075) 68.2,157.25 67.74,157.71 67.74,159.74 C2.2@68.2,160.2 ; R5.1@69.4,160.1 69.3,160.2 C2.2@68.2,160.2
  Signal Layer 2 w0.12: v1(99.675,136.548) 99.675,139.575 99.175,140.075 99.175,143.725 100.05,144.6 v1(100.05,156.075)
  Bottom Layer w0.12: v1(68.2,156.075) v1(100.05,156.075) ; v1(99.675,136.548) 100.023,136.2 102.177,136.2 102.525,136.548 106.127,136.548 107.15,135.525 110.123,135.525 111.325,134.323 111.325,132.982 110.918,132.575 SB44.2@110.1,132.575
MC_PFC_SYNC: C12.2 CN2.27 SB59.2 | length 75.6
  Top Layer w0.12: v1(41.825,150.05) 44.975,150.05 45.95,151.025 45.95,152.425 47.475,153.95 47.475,154.3 48.725,155.55 51.975,155.55 52.825,154.7 53.804,154.7 54.809,155.705 60.27,155.705 61.75,154.225 66.95,154.225 70.125,157.4 C12.2@72.4,157.4 72.6,157.6 72.6,160.8 71.45,161.95 71.45,166.392 CN2.27@70.202,167.64
  Signal Layer 2 w0.12: v1(38.225,127.975) 38.225,128.75 41.15,131.675 41.15,149.375 v1(41.825,150.05)
  Bottom Layer w0.12: v1(38.225,127.975) 38.586,127.975 40.317,126.244 SB59.2@40.317,124.864
MC_PFC_VAC: C5.2 CN2.32 SB57.2 | length 103
  Top Layer w0.12: v1(64.8,159.5) 64.8,160.025 64.675,160.15 C5.2@64.1,160.15 64.1,162.3 65.122,163.322 CN2.32@65.122,165.1
  Signal Layer 2 w0.12: v1(123.35,125.6) 123.35,141.35 123.85,141.85 v1(123.85,157.275)
  Bottom Layer w0.12: v1(64.8,159.5) 68.42,159.5 68.585,159.335 68.775,159.145 93.7,159.145 93.792,159.053 115.825,159.053 117.603,157.275 v1(123.85,157.275) ; SB57.2@118.825,125.6 v1(123.35,125.6)
MC_PWM_1H: CN2.3 SB29.2 | length 50
  Signal Layer 2 w0.12: v1(84.875,142.85) 84.875,144.348 85.575,145.048 v1(85.575,155.225) ; CN2.3@100.682,167.64 101.95,166.371 v1(101.95,155.975)
  Bottom Layer w0.12: SB29.2@78.825,138.775 79.1,139.05 80.348,139.05 81.298,140 81.9,140 82.1,140.2 82.1,141.35 83.605,142.855 84.87,142.855 v1(84.875,142.85) ; v1(85.575,155.225) 97.15,155.225 97.595,155.67 101.03,155.67 101.335,155.975 v1(101.95,155.975)
MC_PWM_1L: CN2.5 SB61.2 | length 63.7
  Top Layer w0.12: CN2.5@98.142,167.64 99.412,168.91 104.965,168.91 106.175,167.7 v1(106.175,166.225)
  Signal Layer 2 w0.12: v1(105.425,124.675) 105.425,132.318 106.322,133.215 106.322,140.147 106.672,140.497 106.672,150.028 106.175,150.525 v1(106.175,166.225)
  Bottom Layer w0.12: v1(105.425,124.675) 106,124.1 112.325,124.1 113,124.775 114.7,124.775 115.05,124.425 SB61.2@115.05,123.825
MC_PWM_2H: CN2.7 SB30.2 | length 61.7
  Signal Layer 2 w0.12: v1(69.345,155.67) 69.345,151.972 68.655,151.282 68.655,142.742 69.32,142.076 69.32,140.13 70.675,138.775 v1(71.35,138.775) ; CN2.7@95.602,167.64 96.9,166.342 v1(96.9,155.67)
  Bottom Layer w0.12: v1(69.345,155.67) v1(96.9,155.67) ; v1(71.35,138.775) SB30.2@74.3,138.775
MC_PWM_2L: CN2.9 SB50.2 | length 66.7
  Top Layer w0.12: CN2.9@93.062,167.64 94.572,169.15 105.064,169.15 106.724,167.49 116.41,167.49 117.375,166.525 v1(119.792,166.525)
  Signal Layer 2 w0.12: v1(119.15,129.75) 119.15,161.752 119.792,162.394 v1(119.792,166.525)
  Bottom Layer w0.12: SB50.2@117.95,129.75 v1(119.15,129.75)
MC_PWM_3H: CN2.11 SB80.2 | length 75.8
  Top Layer w0.12: CN2.11@90.522,167.64 92.272,169.39 105.46,169.39 v1(106.3,168.55)
  Signal Layer 2 w0.12: v1(102.45,121.325) 102.45,154.6 103.674,155.824 103.674,157.919 103.67,157.923 103.67,160.995 105.625,162.95 105.625,167.875 v1(106.3,168.55)
  Bottom Layer w0.12: v1(102.45,121.325) 103.3,120.475 107.392,120.475 107.406,120.461 107.487,120.461 108,119.948 108,119.175 108.23,118.945 110.33,118.945 110.4,118.875 SB80.2@110.4,118.2
MC_PWM_3L: CN2.13 SB54.2 | length 76.8
  Top Layer w0.12: CN2.13@87.982,167.64 89.972,169.63 106.195,169.63 v1(107.25,168.575)
  Signal Layer 2 w0.12: v1(101.25,130.65) 102.133,131.533 102.133,154.758 103.345,155.97 103.345,161.295 105.075,163.025 105.075,168 106.125,169.05 106.775,169.05 v1(107.25,168.575)
  Bottom Layer w0.12: v1(101.25,130.65) 102.4,130.65 106.475,126.575 112.375,126.575 112.975,127.175 SB54.2@113.825,127.175
MC_TEMP: C13.2 CN2.26 SB51.2 | length 72.7
  Top Layer w0.12: CN2.26@72.742,165.1 72.742,162.008 73.9,160.85 C13.2@73.9,157.4 74.4,157.4 74.6,157.2 74.6,156.475 75.325,155.75 85.825,155.75 88.875,152.7 v1(109.625,152.7)
  Signal Layer 2 w0.12: v1@109.62,152.7 109.62,135.905 111.875,133.65 111.875,129.2 v1(111.7,129.025)
  Bottom Layer w0.12: SB51.2@110.1,128.725 110.4,129.025 v1(111.7,129.025)
MDF1_CCK0: SB119.2 TP37.1 U37.8 | length 52
  Top Layer w0.12: TP37.1@124.75,15.9 U37.8@127.925,15.9
  Signal Layer 2 w0.12: v1(127.3,15.9) 127.3,45.55 127.725,45.975 v1(127.725,49.425)
  Bottom Layer w0.12: SB119.2@115,46.425 115,48.375 115.775,49.15 126.012,49.15 126.287,49.425 v1(127.725,49.425)
MDF1_CCK1: CN7.18 CN29.3 R146.1 SB55.2 SB126.2 | length 346.6
  Top Layer w0.12: CN29.3@141.255,6.965 143.482,4.738 152.478,4.738 153.307,5.567 153.307,10.236 151.782,11.761 v1(145.558,11.761)
  Signal Layer 2 w0.1: 148.1,129.975 148.1,130.408
  Signal Layer 2 w0.12: v1(35.5,128.7) 35.5,116.35 34.45,115.3 34.45,113.694 36.176,111.968 36.176,109.541 34.025,107.389 34.025,89.675 v1(36.8,86.9) ; v1@145.556,11.761 v1(145.556,28.675) v1(145.556,79.65) 145.556,109.281 148.1,111.825 148.1,129.975 ; 148.1,130.408 149.075,131.383 v1(149.075,135.125)
  Bottom Layer w0.12: v1(35.5,128.7) 38.236,128.7 40.061,126.875 SB55.2@45.45,126.875 ; v1(36.8,86.9) 38.6,88.7 45.275,88.7 46.65,87.325 46.65,84.527 48.102,83.075 74.729,83.075 78.559,79.245 126.28,79.245 126.65,78.875 144.781,78.875 v1(145.556,79.65) ; SB126.2@127.675,32.225 127.675,30.4 128.45,29.625 144.606,29.625 v1(145.556,28.675) ; CN7.18@146.8,135.128 146.822,135.15 146.847,135.125 v1(149.075,135.125) 149.075,134.375 149.325,134.125 R146.1@149.1,133.9
MDF1_SDIN0: R220.1 TP38.1 U37.13 | length 164
  Top Layer w0.12: U37.13@130.275,15.9 130.35,15.9 130.675,15.575 130.675,15.3 131.225,14.75 132.1,14.75 TP38.1@133.25,15.9 133.25,13.55 v1(133.725,13.075)
  Signal Layer 2 w0.12: v1(52.975,17.125) 52.975,71.15 52.475,71.65 52.475,85.8 52.995,86.32 v1(52.995,89.28)
  Bottom Layer w0.12: R220.1@51.409,89.646 51.525,89.53 51.525,89.28 v1(52.995,89.28) ; v1(52.975,17.125) 98,17.125 101.65,13.475 115.975,13.475 116.375,13.075 v1(133.725,13.075)
MDF1_SDIN3: CN7.17 CN29.5 JP30.2 SB105.2 | length 250.6
  Top Layer w0.12: v1(75.45,99.4) 75.555,99.505 76.918,99.505 96.88,99.505 97.45,100.075 110.15,100.075 114.375,104.3 131.11,104.3 132.325,103.085 134.871,103.085 134.906,103.05 v1(153.125,103.05) ; CN29.5@142.525,6.965 144.288,5.202 152.196,5.202 152.829,5.835 152.829,9.92 151.534,11.216 v1(146.604,11.216)
  Signal Layer 2 w0.12: v1(146.604,11.216) 146.604,25.054 149.45,27.9 JP30.2@149.45,30.68 150.75,31.98 150.75,70.525 153.125,72.9 v1(153.125,103.05) 153.125,116.95 151.33,118.745 v1(151.33,137.128)
  Bottom Layer w0.1: CN7.17@146.8,137.128 148.1,137.128
  Bottom Layer w0.12: SB105.2@61.075,99.4 v1(75.45,99.4) ; 148.1,137.128 v1(151.33,137.128)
